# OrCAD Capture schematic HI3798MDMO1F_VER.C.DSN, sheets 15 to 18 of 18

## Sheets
15 SHEET_04: size A3
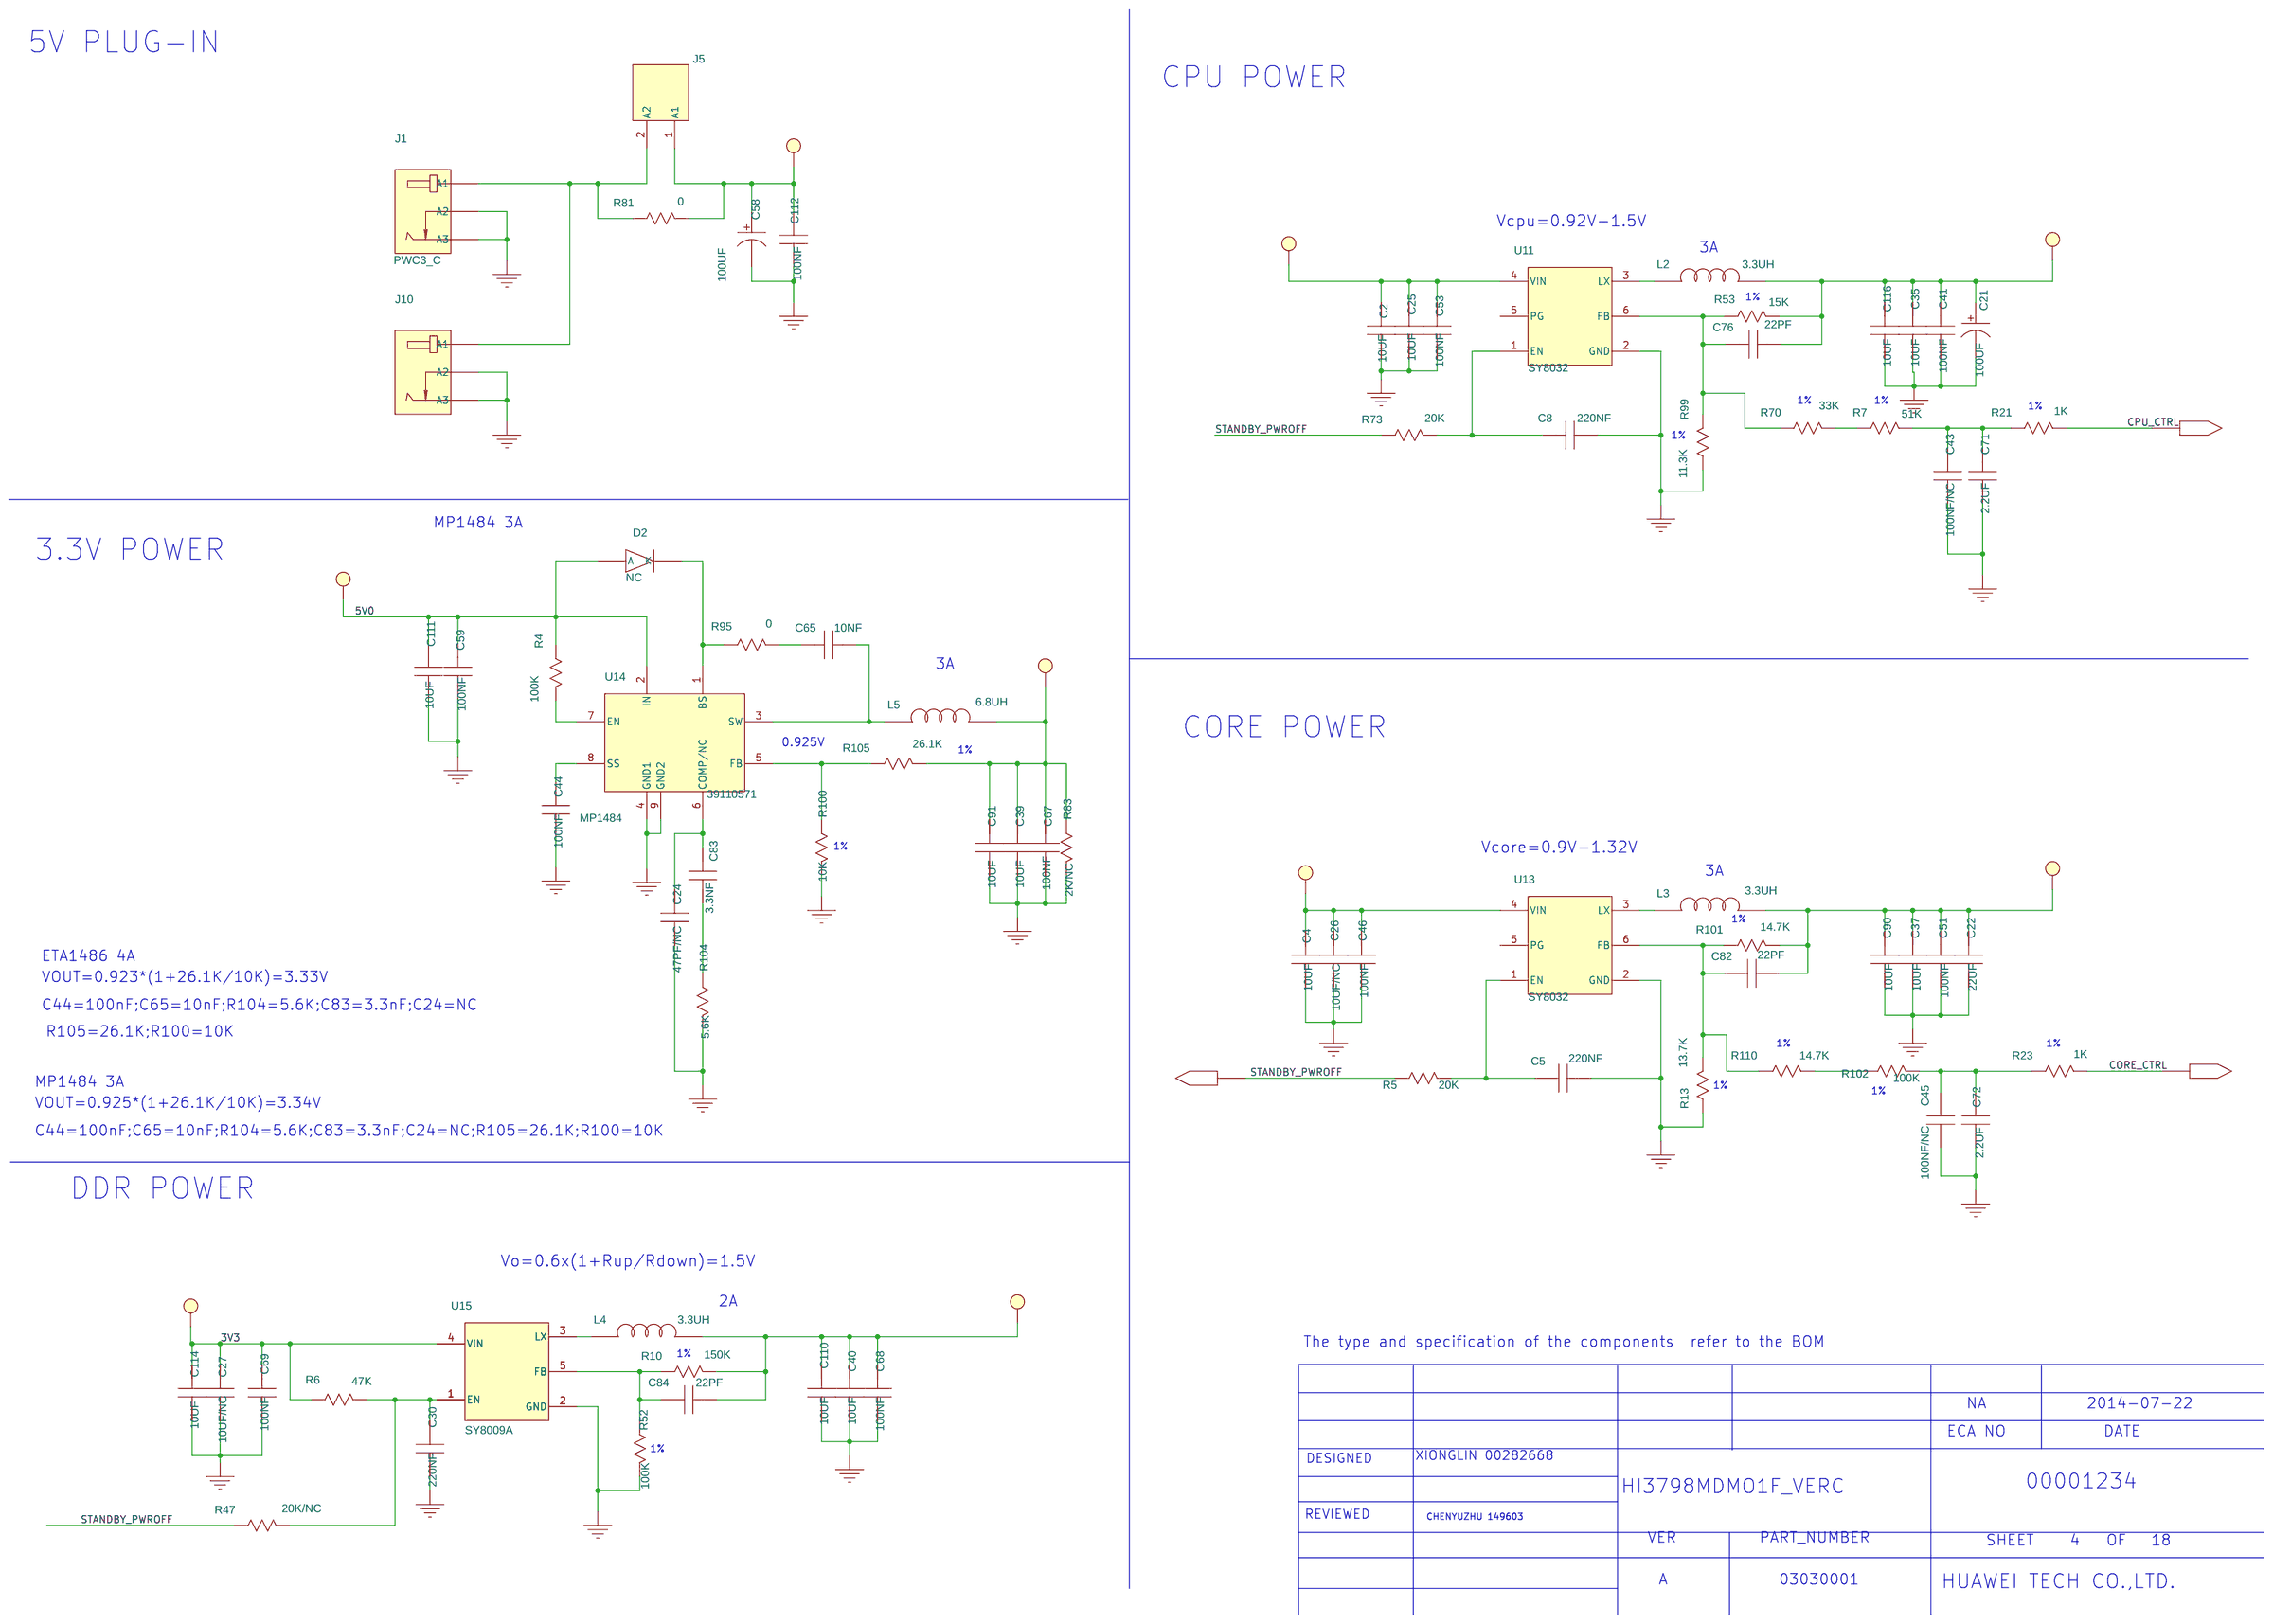
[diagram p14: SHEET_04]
16 SHEET_03: size A3
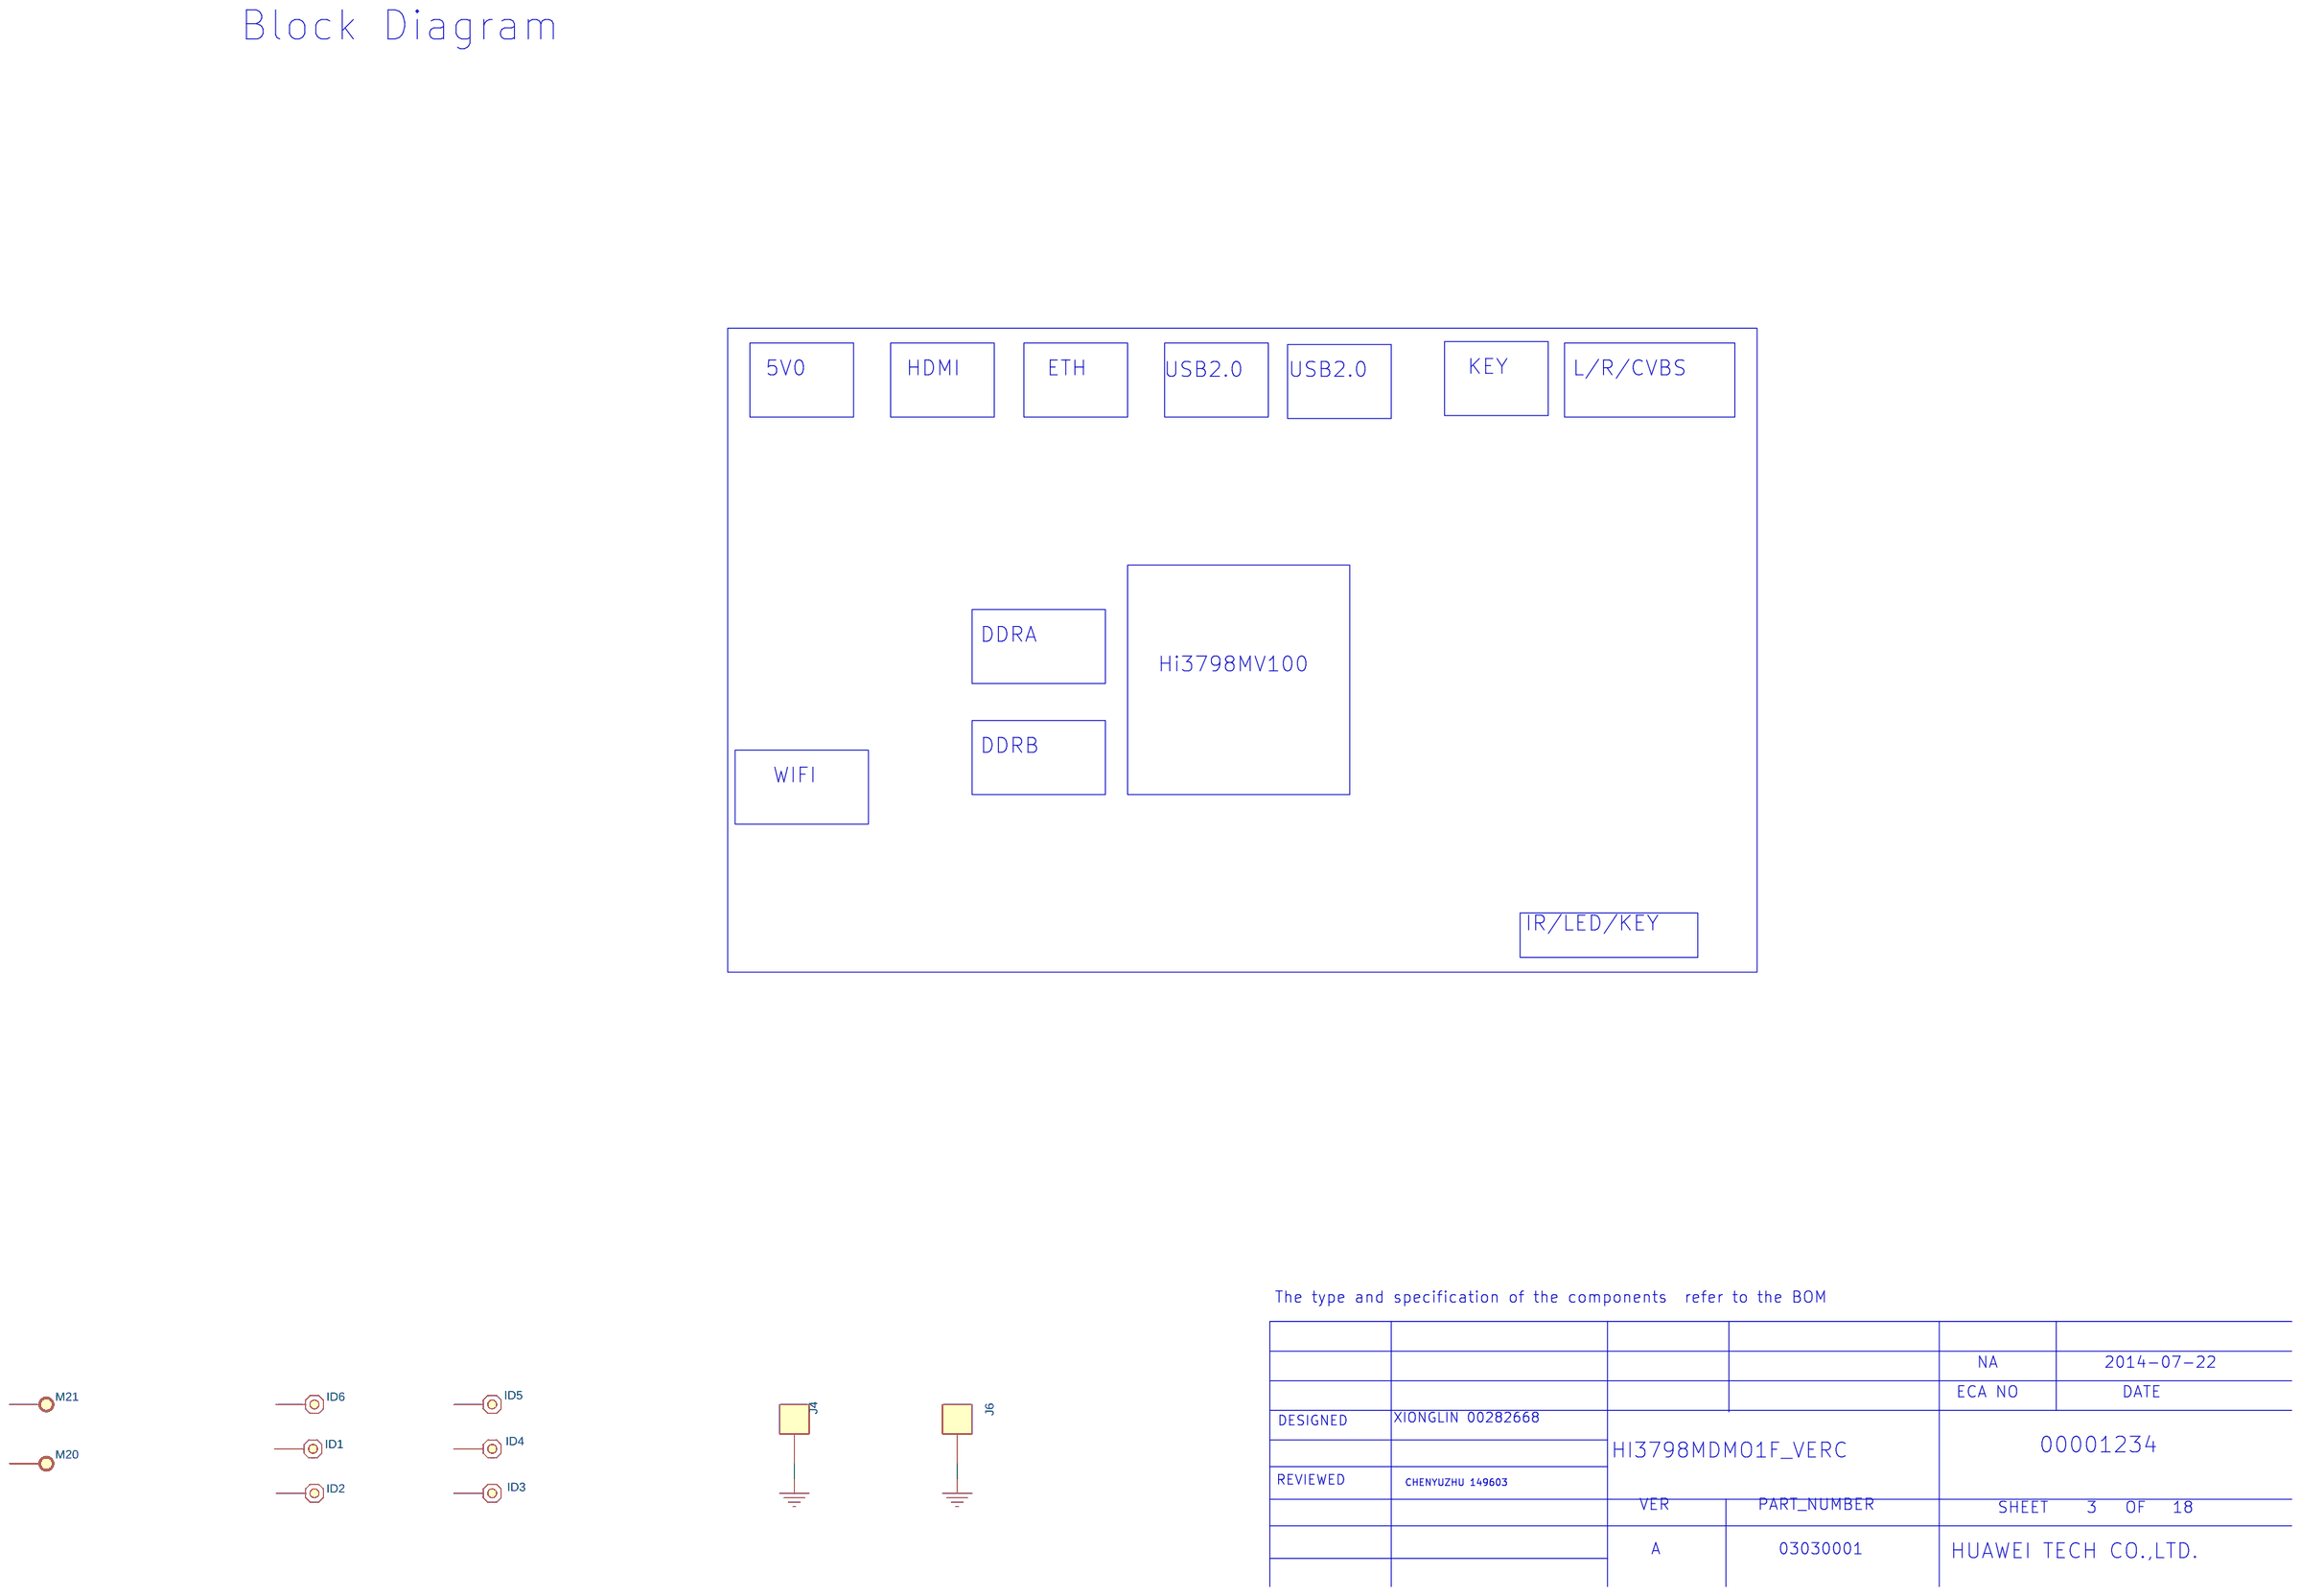
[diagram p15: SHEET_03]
17 SHEET_02
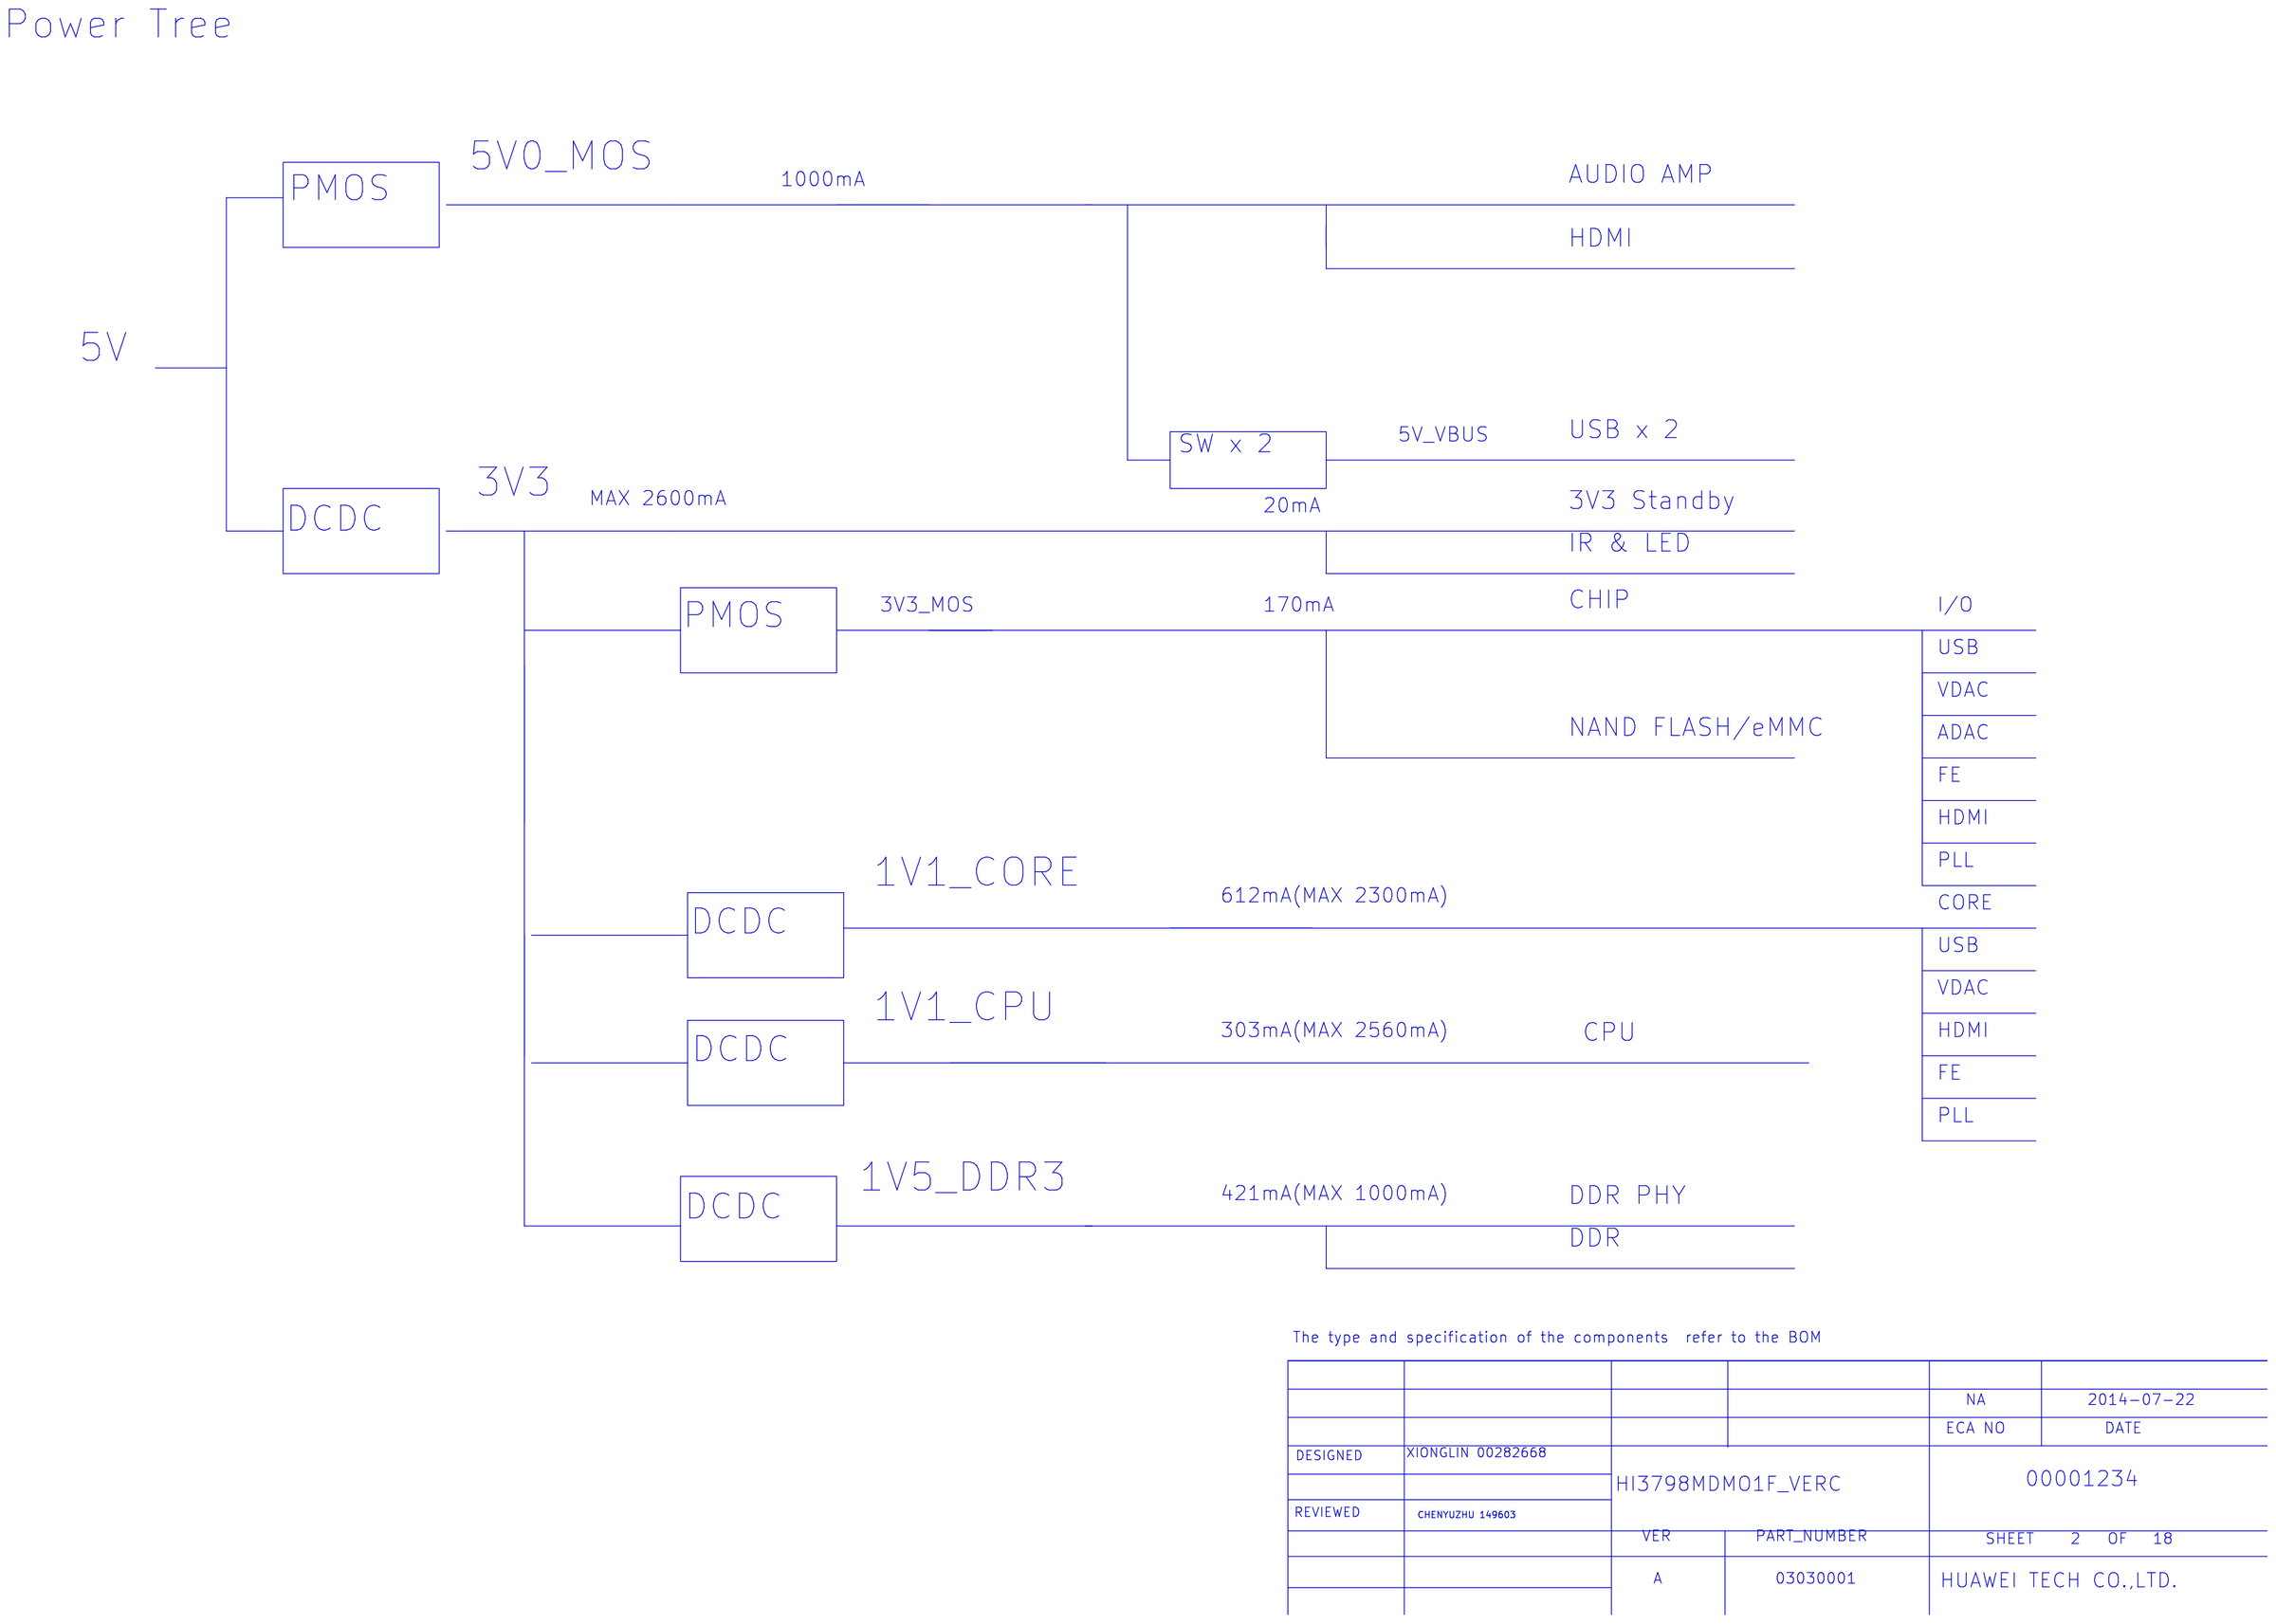
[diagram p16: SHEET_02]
18 SHEET_01
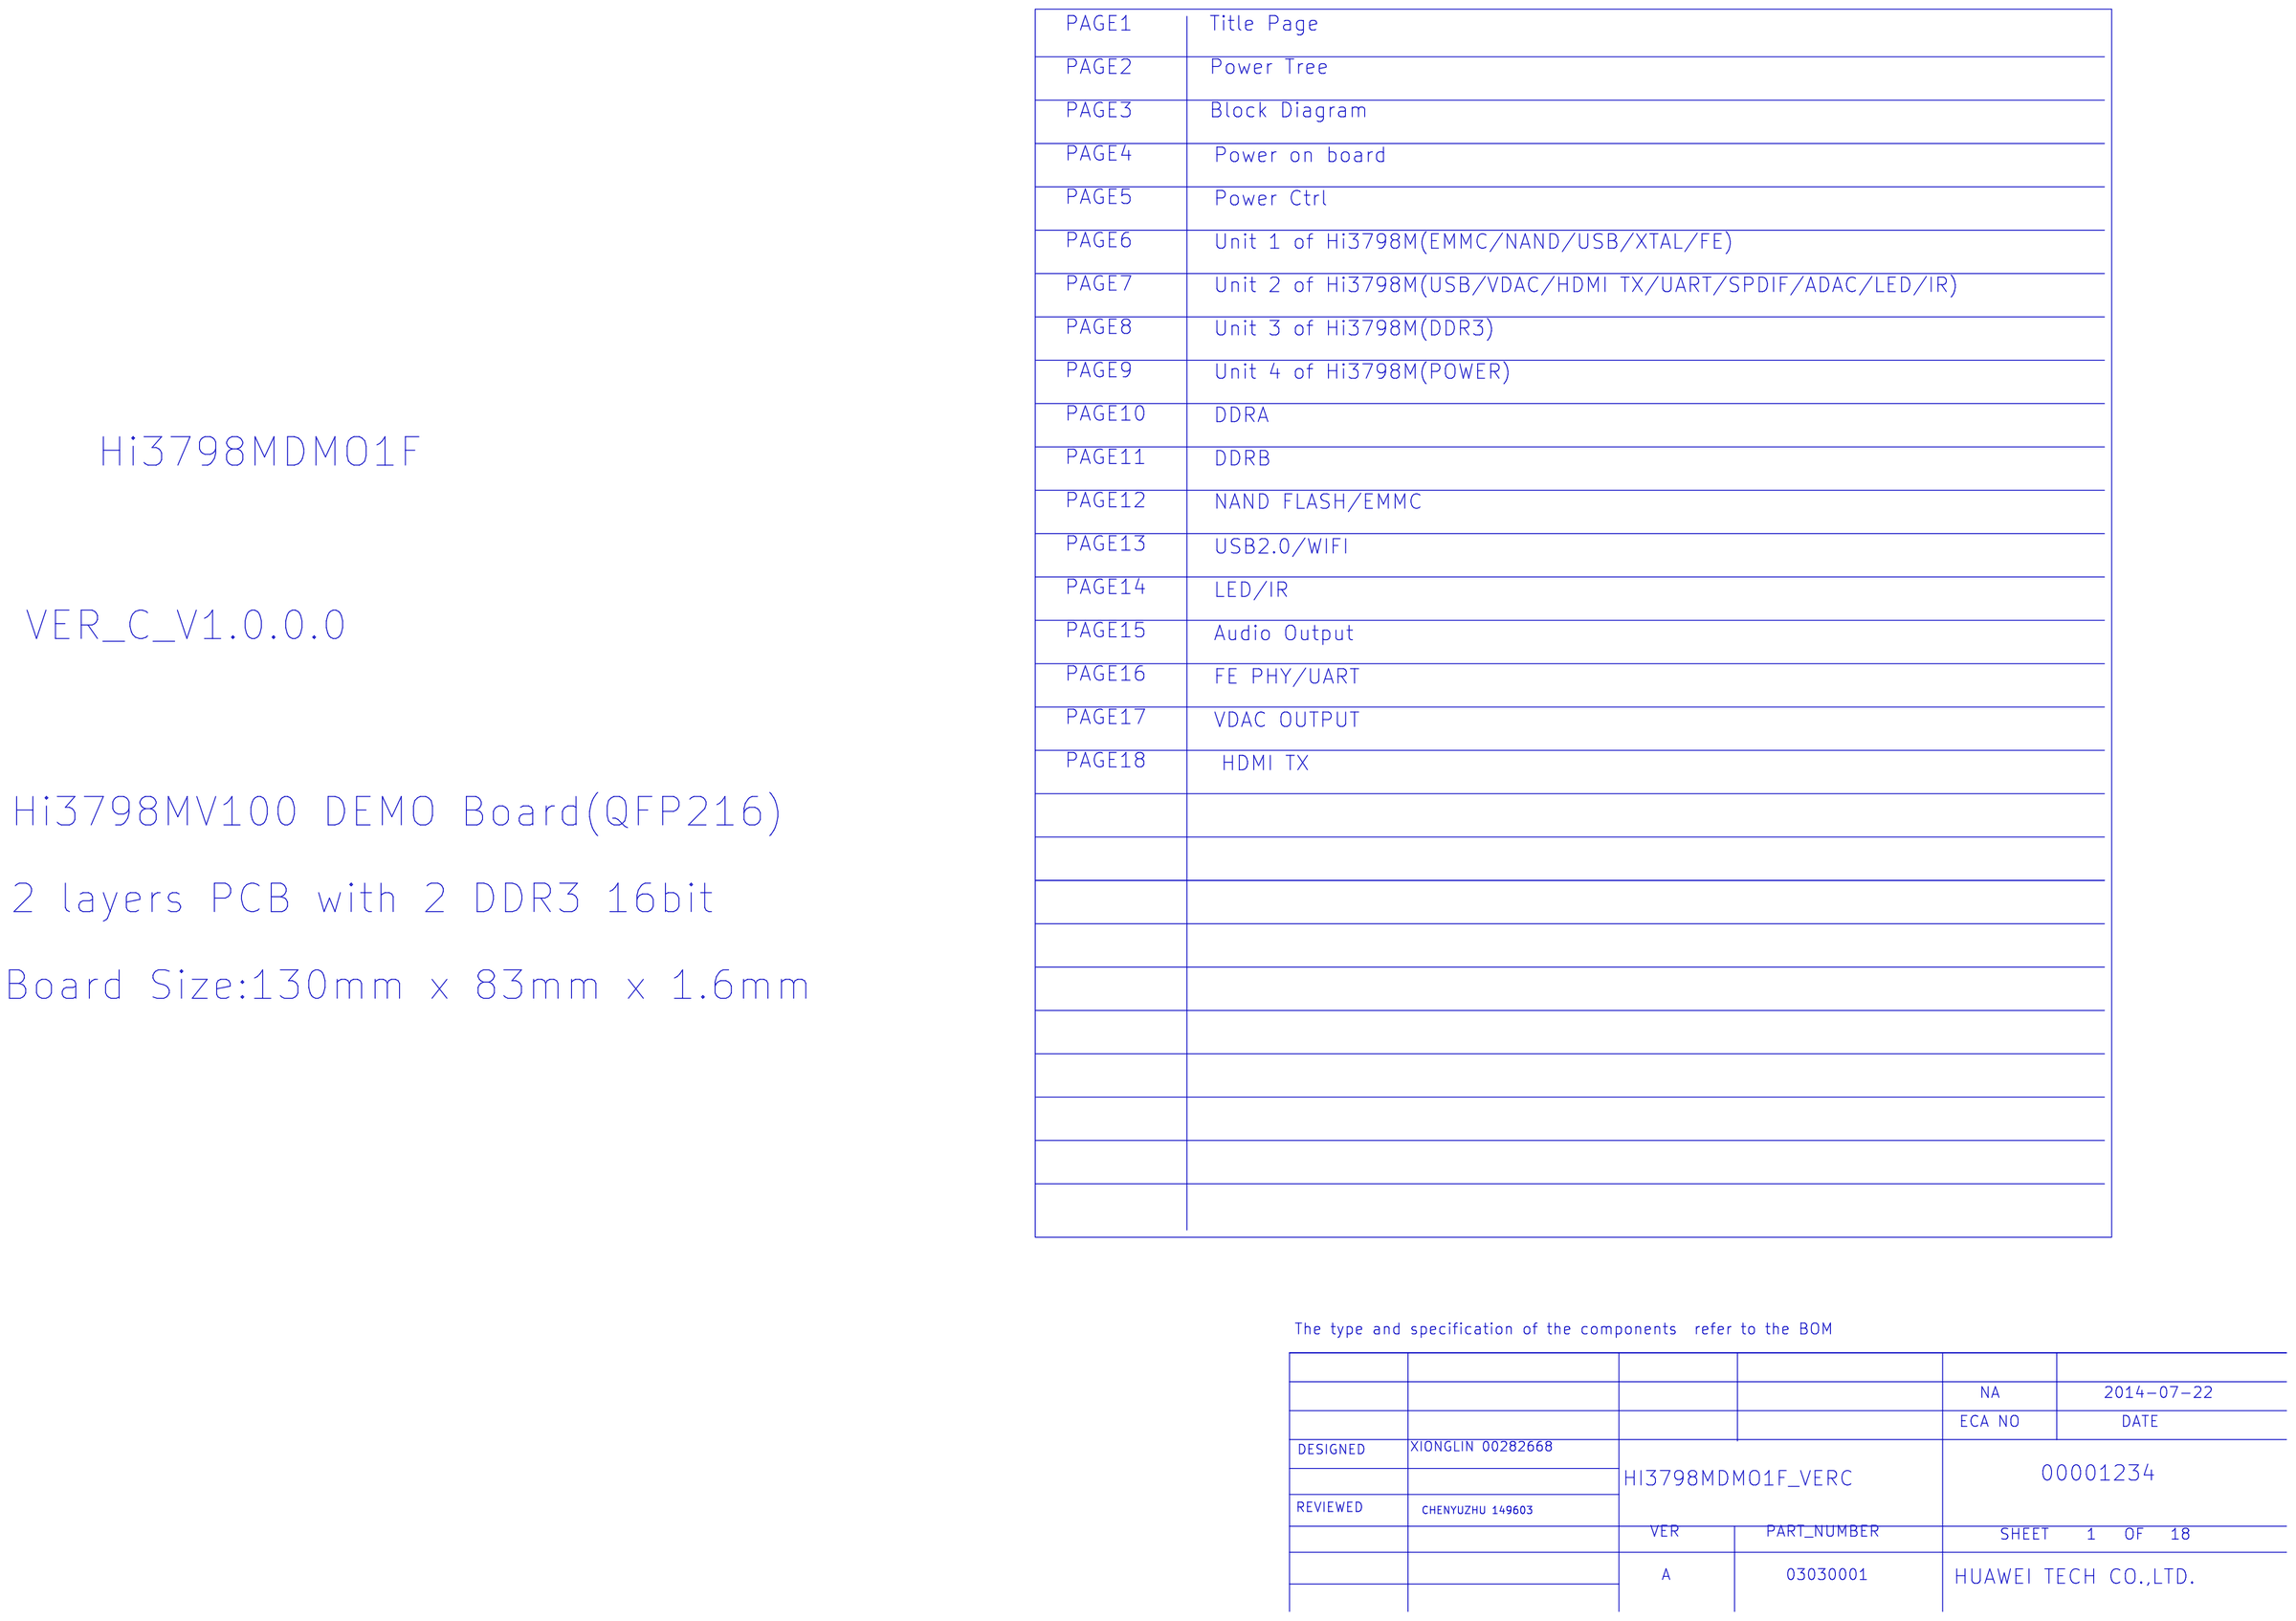
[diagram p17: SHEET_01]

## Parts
sheet SHEET_03
ID1  ID-BOARD  [ID-BOARD]
ID2  ID-BOARD  [ID-BOARD]
ID3  ID-BOARD  [ID-BOARD]
ID4  ID-BOARD  [ID-BOARD]
ID5  ID-BOARD  [ID-BOARD]
ID6  ID-BOARD  [ID-BOARD]
J4  NC  [SIP-1P]
J6  NC  [SIP-1P]
M20  HOLE  [HOLE182-142]
M21  HOLE  [HOLE182-142]
sheet SHEET_04
C2  10UF  [SC0805]
C4  10UF  [SC0805]
C5  220NF  [SC0402]
C8  220NF  [SC0402]
C21  100UF  [SAC6666]
C22  22UF  [SC1206]
C24  47PF/NC  [SC0402]
C25  10UF  [SC0805]
C26  10UF/NC  [SC0805]
C27  10UF/NC  [SC0805]
C30  220NF  [SC0402]
C35  10UF  [SC0603]
C37  10UF  [SC0603]
C39  10UF  [SC0603]
C40  10UF  [SC0603]
C41  100NF  [SC0402]
C43  100NF/NC  [SC0402]
C44  100NF  [SC0402]
C45  100NF/NC  [SC0402]
C46  100NF  [SC0402]
C51  100NF  [SC0402]
C53  100NF  [SC0402]
C58  100UF  [SAC6666]
C59  100NF  [SC0402]
C65  10NF  [SC0402]
C67  100NF  [SC0402]
C68  100NF  [SC0402]
C69  100NF  [SC0402]
C71  2.2UF  [SC0603]
C72  2.2UF  [SC0603]
C76  22PF  [SC0402]
C82  22PF  [SC0402]
C83  3.3NF  [SC0402]
C84  22PF  [SC0402]
C90  10UF  [SC0603]
C91  10UF  [SC0603]
C110  10UF  [SC0603]
C111  10UF  [SC0805]
C112  100NF  [SC0402]
C114  10UF  [SC0805]
C116  10UF  [SC0603]
D2  NC  [HSOD323A]
J1  PWC3_C  [PWC3-RF-A]
J5  NC  [SIP-2P]
J10  NC  [DC-002]
L2  3.3UH  [SWPA4020S]
L3  3.3UH  [SWPA4020S]
L4  3.3UH  [SWPA4020S]
L5  6.8UH  [SWPA5040S]
R4  100K  [SR0402]
R5  20K  [SR0402]
R6  47K  [SR0402]
R7  51K  [SR0402]
R10  150K  [SR0402]
R13  13.7K  [SR0402]
R21  1K  [SR0402]
R23  1K  [SR0402]
R47  20K/NC  [SR0402]
R52  100K  [SR0402]
R53  15K  [SR0402]
R70  33K  [SR0402]
R73  20K  [SR0402]
R81  0  [SR1206]
R83  2K/NC  [SR0805]
R95  0  [SR0402]
R99  11.3K  [SR0402]
R100  10K  [SR0402]
R101  14.7K  [SR0402]
R102  100K  [SR0402]
R104  5.6K  [SR0402]
R105  26.1K  [SR0402]
R110  14.7K  [SR0402]
U11  SY8032  [SOT23_6]
U13  SY8032  [SOT23_6]
U14  MP1484  [SOIC8N]
U15  SY8009A  [SOT23_5]

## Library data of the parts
ID1-ID6 = ID-BOARD: %195%%232%%202%%246%: PCB-MARK点ID-BOARD，亮铜直径40MIL，阻焊开窗直径80MIL，MARK点大小120MIL。; DEVICE: PCB_MARKPOINT_A
J4 J6 = SIP1: %195%%232%%202%%246%: 插针-普通方脚插针-1PIN-单排-直式-5.84MM-2.92MM-2.54MM-THT; %208%%161%%192%%224%%195%%251%%179%%198%: 插针; CODE: 14050101; DEVICE: TSW_101_23_F_S
M20 M21 = HOLE: %195%%232%%202%%246%: 4.0MM铆钉，对应封装孔径162MIL(4.0MM铆接孔的禁布区为300MIL)金属化孔。; DEVICE: RIVET_HOLE162_R4_A
C2 C4 C25-C27 C111 C114 = C: %182%%238%%182%%168%%185%%164%%215%%247%%181%%231%%209%%185%(V): 25; %195%%232%%202%%246%: SMD陶瓷电容-25V-10000NF-+/-20%-X5R-0805; %208%%161%%192%%224%%195%%251%%179%%198%: SMD陶瓷电容; CODE: 8071629; COMPONENT_HIGH_MAX: 1.45MM; DEVICE: C2012X5R1E106KT000N1
C5 C8 C30 = C: %182%%238%%182%%168%%185%%164%%215%%247%%181%%231%%209%%185%(V): 6.3; %195%%232%%202%%246%: SMD陶瓷电容-6.3V-220NF-+/-10%-X5R-0402-BT; %208%%161%%192%%224%%195%%251%%179%%198%: SMD陶瓷电容; CODE: 8070584; COMPONENT_HIGH_MAX: 0.55MM; DEVICE: GRM155R60J224KE01D
C21 C58 = CP: %182%%238%%182%%168%%185%%164%%215%%247%%181%%231%%209%%185%(V): 16; %195%%232%%202%%246%: 非固体SMD铝电容-16V-100UF-+/-20%-6.3*5.4MM-极性-105DEGC-1000H-片式,温度敏感器件-工艺耐温250DEGC,5S; %208%%161%%192%%224%%195%%251%%179%%198%: 非固体SMD铝电容; CODE: 8010269; COMPONENT_HIGH_MAX: 5.7MM; DEVICE: UWT1C101MCL1GB
C22 = C: %182%%238%%182%%168%%185%%164%%215%%247%%181%%231%%209%%185%(V): 6.3; %195%%232%%202%%246%: SMD陶瓷电容-6.3V-47000NF-+/-20%-X5R-1206; %208%%161%%192%%224%%195%%251%%179%%198%: SMD陶瓷电容; CODE: 8070680; COMPONENT_HIGH_MAX: 1.9MM; DEVICE: CM316X5R476M06AT
C24 = C: %182%%238%%182%%168%%185%%164%%215%%247%%181%%231%%209%%185%(V): 50; %195%%232%%202%%246%: SMD陶瓷电容-50V-0.047NF-±5%-NP0-0402; %208%%161%%192%%224%%195%%251%%179%%198%: SMD陶瓷电容; CODE: 8070549; COMPONENT_HIGH_MAX: 0.55MM; DEVICE: C0402C470J5GAC_7867
C35 C37 C39 C40 C90 C91 C110 C116 = C: %182%%238%%182%%168%%185%%164%%215%%247%%181%%231%%209%%185%(V): 6.3; %195%%232%%202%%246%: SMD陶瓷电容-6.3V-10000NF-+/-20%-X5R-0603-BT,TS16949; %208%%161%%192%%224%%195%%251%%179%%198%: SMD陶瓷电容; CODE: 8070649; COMPONENT_HIGH_MAX: 0.9MM; DEVICE: C1608X5R0J106MT0A0E
C41 C43-C46 C51 C53 C59 C67-C69 C112 = C: %182%%238%%182%%168%%185%%164%%215%%247%%181%%231%%209%%185%(V): 16; %195%%232%%202%%246%: SMD陶瓷电容-16V-100NF-±10%-X7R-0402; %208%%161%%192%%224%%195%%251%%179%%198%: SMD陶瓷电容; CODE: 8070614; COMPONENT_HIGH_MAX: 0.6MM; DEVICE: RMEMK105BJ104KV_FR
C65 = C: %182%%238%%182%%168%%185%%164%%215%%247%%181%%231%%209%%185%(V): 16; %195%%232%%202%%246%: SMD陶瓷电容-16V-10NF-+/-10%-X7R-0402; %208%%161%%192%%224%%195%%251%%179%%198%: SMD陶瓷电容; CODE: 8070449; COMPONENT_HIGH_MAX: 0.55MM; DEVICE: GRM155R71C103KA01D
C71 C72 = C: %182%%238%%182%%168%%185%%164%%215%%247%%181%%231%%209%%185%(V): 10; %195%%232%%202%%246%: SMD陶瓷电容-10V-2200NF-+/-10%-X5R-0603; %208%%161%%192%%224%%195%%251%%179%%198%: SMD陶瓷电容; CODE: 8070573; COMPONENT_HIGH_MAX: 0.9MM; DEVICE: GRM188R61A225KE34D
C76 C82 C84 = C: %182%%238%%182%%168%%185%%164%%215%%247%%181%%231%%209%%185%(V): 50; %195%%232%%202%%246%: SMD陶瓷电容-50V-0.022NF-+/-5%-NP0-0402-BT; %208%%161%%192%%224%%195%%251%%179%%198%: SMD陶瓷电容; CODE: 8070545; COMPONENT_HIGH_MAX: 0.55MM; DEVICE: RMUMK105CG220JV_F
C83 = C: %182%%238%%182%%168%%185%%164%%215%%247%%181%%231%%209%%185%(V): 50; %195%%232%%202%%246%: SMD陶瓷电容-50V-3.3NF-±10%-X7R-0402; %208%%161%%192%%224%%195%%251%%179%%198%: SMD陶瓷电容; CODE: 8070621; COMPONENT_HIGH_MAX: 0.55MM; DEVICE: GRM155R71H332KA01D
D2 = D_A: %195%%232%%202%%246%: 肖特基二极管-10V-3A-0.24V-SOD323-BT; %208%%161%%192%%224%%195%%251%%179%%198%: 肖特基二极管; CODE: 15010252; COMPONENT_HIGH_MAX: 1.1MM; DEVICE: BAT60BE6327
J1 = PWC3_C: %195%%232%%202%%246%: IO连接器-DC JACK-3PIN-母座-3.9/1.3MM弯式-5V2A-00482858; CODE: 14240410; COMPONENT_HIGH_MAX: 11.25MM; DEVICE: DC_012_HW
J5 = SIP2: %195%%232%%202%%246%: 插针-普通方脚插针-2PIN-单排-直式-5.84MM-2.92MM-2.54MM-THT; %208%%161%%192%%224%%195%%251%%179%%198%: 插针; CODE: 14050028; COMPONENT_HIGH_MAX: 8.38MM; DEVICE: TSW_102_23_F_S
J10 = PWC3_C: %195%%232%%202%%246%: IO连接器-DC JACK-3PIN-母座-3.9/1.3MM弯式-5V2A-00482858; CODE: *; COMPONENT_HIGH_MAX: 11.25MM; DEVICE: DC_012_HW
L2-L4 = SWPA4020S3R3MT
L5 = SWPA5040S6R8MT
R4 = R: %182%%238%%182%%168%%185%%166%%194%%202%(W): 0.06; %195%%232%%202%%246%: 片式厚膜电阻器-0.0625W-100000OHM-+/-5%-0402; %208%%161%%192%%224%%195%%251%%179%%198%: 片式厚膜电阻器; %215%%232%%214%%181%%212%%202%%208%%237%%198%%171%%178%%238%: +/-5%; CODE: 7090831; COMPONENT_HIGH_MAX: 0.4MM; DEVICE: RK73B1ELTP104J
R5 R47 R73 = R: %182%%238%%182%%168%%185%%166%%194%%202%(W): 0.06; %195%%232%%202%%246%: 片式厚膜电阻器-0.0625W-20000OHM-+/-1%-0402-TS16949; %208%%161%%192%%224%%195%%251%%179%%198%: 片式厚膜电阻器; %215%%232%%214%%181%%212%%202%%208%%237%%198%%171%%178%%238%: +/-1%; CODE: 7091374; COMPONENT_HIGH_MAX: 0.4MM; DEVICE: RC_02W2002FT
R6 = R: %182%%238%%182%%168%%185%%166%%194%%202%(W): 0.06; %195%%232%%202%%246%: 片式厚膜电阻器-0.0625W-47000OHM-+/-5%-0402-ELOM; %208%%161%%192%%224%%195%%251%%179%%198%: 片式厚膜电阻器; %215%%232%%214%%181%%212%%202%%208%%237%%198%%171%%178%%238%: +/-5%; CODE: 7090819; COMPONENT_HIGH_MAX: 0.4MM; DEVICE: RC0402JR_0747K
R7 = R: %182%%238%%182%%168%%185%%166%%194%%202%(W): 0.06; %195%%232%%202%%246%: 片式厚膜电阻器-0.0625W-51000OHM-+/-1%-0402; %208%%161%%192%%224%%195%%251%%179%%198%: 片式厚膜电阻器; %215%%232%%214%%181%%212%%202%%208%%237%%198%%171%%178%%238%: +/-1%; CODE: 7091384; COMPONENT_HIGH_MAX: 0.4MM; DEVICE: RC_02W5102FT
R10 = R: %182%%238%%182%%168%%185%%166%%194%%202%(W): 0.06; %195%%232%%202%%246%: 片式厚膜电阻器-0.0625W-150000OHM-+/-1%-0402; %208%%161%%192%%224%%195%%251%%179%%198%: 片式厚膜电阻器; %215%%232%%214%%181%%212%%202%%208%%237%%198%%171%%178%%238%: +/-1%; CODE: 7090833; COMPONENT_HIGH_MAX: 0.4MM; DEVICE: RK73H1ELTP1503F
R13 = R: %182%%238%%182%%168%%185%%166%%194%%202%(W): 0.06; %195%%232%%202%%246%: 片式厚膜电阻器-0.0625W-13700OHM-+/- 1%-0402-供电专用-供电专用; %208%%161%%192%%224%%195%%251%%179%%198%: 片式厚膜电阻器; %215%%232%%214%%181%%212%%202%%208%%237%%198%%171%%178%%238%: +/- 1%; CODE: 7091435; COMPONENT_HIGH_MAX: 0.4MM; DEVICE: RC0402FR_0713K7L
R21 R23 = R: %182%%238%%182%%168%%185%%166%%194%%202%(W): 0.1; %195%%232%%202%%246%: 片式厚膜电阻器-0.1W-1000OHM-+/-1%-0603; %208%%161%%192%%224%%195%%251%%179%%198%: 片式厚膜电阻器; %215%%232%%214%%181%%212%%202%%208%%237%%198%%171%%178%%238%: +/-1%; CODE: 7092250; COMPONENT_HIGH_MAX: 0.5MM; DEVICE: RK73H1JTTD1001F
R52 = R: %182%%238%%182%%168%%185%%166%%194%%202%(W): 0.06; %195%%232%%202%%246%: 片式厚膜电阻器-0.0625W-100000OHM-+/-5%-0402-BT; %208%%161%%192%%224%%195%%251%%179%%198%: 片式厚膜电阻器; %215%%232%%214%%181%%212%%202%%208%%237%%198%%171%%178%%238%: +/-5%; CODE: 7090831; COMPONENT_HIGH_MAX: 0.4MM; DEVICE: RK73B1ELTP104J
R53 = R: %182%%238%%182%%168%%185%%166%%194%%202%(W): 0.06; %195%%232%%202%%246%: 片式厚膜电阻器-0.0625W-15000OHM-+/-1%-0402-BT; %208%%161%%192%%224%%195%%251%%179%%198%: 片式厚膜电阻器; %215%%232%%214%%181%%212%%202%%208%%237%%198%%171%%178%%238%: +/-1%; CODE: 7091372; COMPONENT_HIGH_MAX: 0.4MM; DEVICE: RC_02W1502FT
R70 = R: %182%%238%%182%%168%%185%%166%%194%%202%(W): 0.06; %195%%232%%202%%246%: 片式厚膜电阻器-0.0625W-33000OHM-+/-5%-0402; %208%%161%%192%%224%%195%%251%%179%%198%: 片式厚膜电阻器; %215%%232%%214%%181%%212%%202%%208%%237%%198%%171%%178%%238%: +/-5%; CODE: 7090828; COMPONENT_HIGH_MAX: 0.4MM; DEVICE: RK73B1ELTP333J
R81 = R: %182%%238%%182%%168%%185%%166%%194%%202%(W): 0.25; %195%%232%%202%%246%: 片式厚膜电阻器-0.25W-0OHM-<50MOHM-1206-2A-BT; %208%%161%%192%%224%%195%%251%%179%%198%: 片式厚膜电阻器; %215%%232%%214%%181%%212%%202%%208%%237%%198%%171%%178%%238%: <50MOHM; CODE: 7090002; COMPONENT_HIGH_MAX: 0.7MM; DEVICE: RC1206JR_070RL
R83 = R: %182%%238%%182%%168%%185%%166%%194%%202%(W): 0.13; %195%%232%%202%%246%: 片式厚膜电阻器-0.125W-2000OHM-+/-1%-0805; %208%%161%%192%%224%%195%%251%%179%%198%: 片式厚膜电阻器; %215%%232%%214%%181%%212%%202%%208%%237%%198%%171%%178%%238%: +/-1%; CODE: 7090225; COMPONENT_HIGH_MAX: 0.65MM; DEVICE: RK73H2ATTD2001F
R95 = R: %182%%238%%182%%168%%185%%166%%194%%202%(W): 0.06; %195%%232%%202%%246%: 片式厚膜电阻器-0.0625W-0OHM-< 50MOHM-0402-1A-BT; %208%%161%%192%%224%%195%%251%%179%%198%: 片式厚膜电阻器; %215%%232%%214%%181%%212%%202%%208%%237%%198%%171%%178%%238%: < 50MOHM; CODE: 7090800; DEVICE: RC0402JR_070R
R99 = R: %182%%238%%182%%168%%185%%166%%194%%202%(W): 0.06; %195%%232%%202%%246%: 片式厚膜电阻器-0.0625W-11300OHM-+/-1%-0402; %208%%161%%192%%224%%195%%251%%179%%198%: 片式厚膜电阻器; %215%%232%%214%%181%%212%%202%%208%%237%%198%%171%%178%%238%: +/-1%; CODE: 7090816; COMPONENT_HIGH_MAX: 0.4MM; DEVICE: RC0402FR_0711K3
R100 = R: %182%%238%%182%%168%%185%%166%%194%%202%(W): 0.06; %195%%232%%202%%246%: 片式厚膜电阻器-0.0625W-10000OHM-+/-1%-0402-BT; %208%%161%%192%%224%%195%%251%%179%%198%: 片式厚膜电阻器; %215%%232%%214%%181%%212%%202%%208%%237%%198%%171%%178%%238%: +/-1%; CODE: 7090867; COMPONENT_HIGH_MAX: 0.4MM; DEVICE: RK73H1ETTP1002F
R101 R110 = R: %182%%238%%182%%168%%185%%166%%194%%202%(W): 0.06; %195%%232%%202%%246%: 片式厚膜电阻器-0.0625W-14700OHM-+/-1%-0402; %208%%161%%192%%224%%195%%251%%179%%198%: 片式厚膜电阻器; %215%%232%%214%%181%%212%%202%%208%%237%%198%%171%%178%%238%: +/-1%; CODE: *; COMPONENT_HIGH_MAX: 0.4MM; DEVICE: RK73H1ETTD7502F
R102 = R: %182%%238%%182%%168%%185%%166%%194%%202%(W): 0.06; %195%%232%%202%%246%: 片式厚膜电阻器-0.0625W-100000OHM-+/-1%-0402; %208%%161%%192%%224%%195%%251%%179%%198%: 片式厚膜电阻器; %215%%232%%214%%181%%212%%202%%208%%237%%198%%171%%178%%238%: +/-1%; CODE: 7090875; COMPONENT_HIGH_MAX: 0.4MM; DEVICE: RK73H1ETTP1003F
R104 = R: %182%%238%%182%%168%%185%%166%%194%%202%(W): 0.06; %195%%232%%202%%246%: 片式厚膜电阻器-0.0625W-5600OHM-+/-1%-0402-BT; %208%%161%%192%%224%%195%%251%%179%%198%: 片式厚膜电阻器; %215%%232%%214%%181%%212%%202%%208%%237%%198%%171%%178%%238%: +/-1%; CODE: 7091275; COMPONENT_HIGH_MAX: 0.4MM; DEVICE: RK73H1ETTP5601F
R105 = R: %182%%238%%182%%168%%185%%166%%194%%202%(W): 0.06; %195%%232%%202%%246%: 片式厚膜电阻器-0.0625W-26100OHM-+/-1%-0402; %208%%161%%192%%224%%195%%251%%179%%198%: 片式厚膜电阻器; %215%%232%%214%%181%%212%%202%%208%%237%%198%%171%%178%%238%: +/-5%; CODE: *; COMPONENT_HIGH_MAX: 0.4MM; DEVICE: RK73B1ETTP273J
U11 U13 = SY8032
U14 = MP1484: CODE: 39110571
U15 = SY8009A

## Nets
1V1_CORE: C22.1(A) C37.1(A) C51.1(A) C82.2(B) C90.1(A) L3.2(B) R101.2(B) ; also on sheet 10 12 13
1V1_CPU: C21.1 C35.1(A) C41.1(A) C76.2(B) C116.1(A) L2.2(B) R53.2(B) ; also on sheet 10
1V5_DDR3: C40.1(A) C68.1(A) C84.2(B) C110.1(A) L4.2(B) R10.2(B) ; also on sheet 8 9 11
3V3: C2.1(A) C4.1(A) C25.1(A) C26.1(A) C27.1(A) C39.1(A) C46.1(A) C53.1(A) C67.1(A) C69.1(A) C91.1(A) C114.1(A) L5.2(B) R6.1(A) R83.1(A) R105.2(B) U11.4(VIN) U13.4(VIN) U15.4(VIN) ; also on sheet 3 5 10 13 14
5V0: C58.1 C59.1(A) C111.1(A) C112.1(A) D2.2(A) J5.1(A1) R4.1(A) R81.2(B) U14.2(IN) ; also on sheet 14
GND: C2.2(B) C4.2(B) C5.2(B) C8.2(B) C21.2 C22.2(B) C24.2(B) C25.2(B) C26.2(B) C27.2(B) C30.2(B) C35.2(B) C37.2(B) C39.2(B) C40.2(B) C41.2(B) C43.2(B) C44.2(B) C45.2(B) C46.2(B) C51.2(B) C53.2(B) C58.2 C59.2(B) C67.2(B) C68.2(B) C69.2(B) C71.2(B) C72.2(B) C90.2(B) C91.2(B) C110.2(B) C111.2(B) C112.2(B) C114.2(B) C116.2(B) J1.2(A2) J1.3(A3) J4.1 J6.1 J10.2(A2) J10.3(A3) R13.1(A) R52.2(B) R83.2(B) R99.1(A) R100.2(B) R104.2(B) U11.2(GND) U13.2(GND) U14.4(GND1) U14.9(GND2) U15.2(GND) ; also on sheet 1 2 3 4 5 6 7 8 9 10 11 12 13 14
CORE_CTRL: R23.2(B) ; also on sheet 12
CPU_CTRL: R21.2(B) ; also on sheet 12
STANDBY_PWROFF: R5.1(A) R47.1(A) R73.1(A) ; also on sheet 13 14
N338390: C82.1(A) R13.2(B) R101.1(A) R110.1(A) U13.6(FB)
N338426: C5.1(A) R5.2(B) U13.1(EN)
N338674: C76.1(A) R53.1(A) R70.1(A) R99.2(B) U11.6(FB)
N338710: C8.1(A) R73.2(B) U11.1(EN)
N338726: L3.1(A) U13.3(LX)
N338730: C45.1(A) C72.1(A) R23.1(A) R102.2(B)
N338750: L2.1(A) U11.3(LX)
N338754: C43.1(A) C71.1(A) R7.2(B) R21.1(A)
N338774: L4.1(A) U15.3(LX)
N338830: R7.1(A) R70.2(B)
N338834: C65.2(B) L5.1(A) U14.3(SW)
N338850: C65.1(A) R95.2(B)
N338854: C44.1(A) U14.8(SS)
N338862: R4.2(B) U14.7(EN)
N338870: C24.1(A) C83.1(A) U14.6(COMP/NC)
N338886: C83.2(B) R104.1(A)
N338890: R100.1(A) R105.1(A) U14.5(FB)
N338902: C30.1(A) R6.2(B) R47.2(B) U15.1(EN)
N338986: J1.1(A1) J5.2(A2) J10.1(A1) R81.1(A)
N339078: D2.1(K) R95.1(A) U14.1(BS)
N339094: R102.1(A) R110.2(B)
N339098: C84.1(A) R10.1(A) R52.1(A) U15.5(FB)

Not connected (* = marked no-connect by the designer): ID1 1; ID2 1; ID3 1; ID4 1; ID5 1; ID6 1; M20 1(GND); M21 1(GND); U11 5(PG); U13 5(PG)

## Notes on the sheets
sheet 15
- 5V PLUG-IN
- CPU POWER
- Vcpu=0.92V-1.5V
- 3A
- 1%
- 1%
- 1%
- 1%
- 1%
- MP1484 3A
- 3.3V POWER
- 3A
- CORE POWER
- 0.925V
- 1%
- 1%
- Vcore=0.9V-1.32V
- 3A
- 1%
- ETA1486 4A
- VOUT=0.923*(1+26.1K/10K)=3.33V
- C44=100nF;C65=10nF;R104=5.6K;C83=3.3nF;C24=NC
- R105=26.1K;R100=10K
- 1%
- 1%
- MP1484 3A
- 1%
- 1%
- VOUT=0.925*(1+26.1K/10K)=3.34V
- C44=100nF;C65=10nF;R104=5.6K;C83=3.3nF;C24=NC;R105=26.1K;R100=10K
- DDR POWER
- Vo=0.6x(1+Rup/Rdown)=1.5V
- 2A
- 1%
- The type and specification of the components  refer to the BOM
- NA
- 2014-07-22
- ECA NO
- DATE
- 1%
- XIONGLIN 00282668
- DESIGNED
- HI3798MDMO1F_VERC
- 00001234
- REVIEWED
- CHENYUZHU 149603
- VER
- PART_NUMBER
- SHEET
- 4
- OF
- 18
- A
- 03030001
- HUAWEI TECH CO.,LTD.
sheet 16
- Block Diagram
- 5V0
- HDMI
- ETH
- USB2.0
- USB2.0
- KEY
- L/R/CVBS
- DDRA
- Hi3798MV100
- DDRB
- WIFI
- IR/LED/KEY
- The type and specification of the components  refer to the BOM
- NA
- 2014-07-22
- ECA NO
- DATE
- XIONGLIN 00282668
- DESIGNED
- HI3798MDMO1F_VERC
- 00001234
- REVIEWED
- CHENYUZHU 149603
- VER
- PART_NUMBER
- SHEET
- 3
- OF
- 18
- A
- 03030001
- HUAWEI TECH CO.,LTD.
sheet 17
- Power Tree
- 5V0_MOS
- 1000mA
- AUDIO AMP
- PMOS
- HDMI
- 5V
- USB x 2
- SW x 2
- 5V_VBUS
- 3V3
- MAX 2600mA
- 3V3 Standby
- DCDC
- 20mA
- IR & LED
- CHIP
- PMOS
- 3V3_MOS
- 170mA
- I/O
- USB
- VDAC
- NAND FLASH/eMMC
- ADAC
- FE
- HDMI
- 1V1_CORE
- PLL
- 612mA(MAX 2300mA)
- DCDC
- CORE
- USB
- 1V1_CPU
- VDAC
- 303mA(MAX 2560mA)
- CPU
- HDMI
- DCDC
- FE
- PLL
- 1V5_DDR3
- DCDC
- 421mA(MAX 1000mA)
- DDR PHY
- DDR
- The type and specification of the components  refer to the BOM
- NA
- 2014-07-22
- ECA NO
- DATE
- DESIGNED
- XIONGLIN 00282668
- HI3798MDMO1F_VERC
- 00001234
- REVIEWED
- CHENYUZHU 149603
- VER
- PART_NUMBER
- SHEET
- 2
- OF
- 18
- A
- 03030001
- HUAWEI TECH CO.,LTD.
sheet 18
- PAGE1
- Title Page
- PAGE2
- Power Tree
- PAGE3
- Block Diagram
- PAGE4
- Power on board
- PAGE5
- Power Ctrl
- PAGE6
- Unit 1 of Hi3798M(EMMC/NAND/USB/XTAL/FE)
- PAGE7
- Unit 2 of Hi3798M(USB/VDAC/HDMI TX/UART/SPDIF/ADAC/LED/IR)
- PAGE8
- Unit 3 of Hi3798M(DDR3)
- PAGE9
- Unit 4 of Hi3798M(POWER)
- PAGE10
- DDRA
- Hi3798MDMO1F
- PAGE11
- DDRB
- PAGE12
- NAND FLASH/EMMC
- PAGE13
- USB2.0/WIFI
- PAGE14
- LED/IR
- VER_C_V1.0.0.0
- PAGE15
- Audio Output
- PAGE16
- FE PHY/UART
- PAGE17
- VDAC OUTPUT
- PAGE18
- HDMI TX
- Hi3798MV100 DEMO Board(QFP216)
- 2 layers PCB with 2 DDR3 16bit
- Board Size:130mm x 83mm x 1.6mm
- The type and specification of the components  refer to the BOM
- NA
- 2014-07-22
- ECA NO
- DATE
- DESIGNED
- XIONGLIN 00282668
- 00001234
- HI3798MDMO1F_VERC
- REVIEWED
- CHENYUZHU 149603
- VER
- PART_NUMBER
- SHEET
- 1
- OF
- 18
- A
- 03030001
- HUAWEI TECH CO.,LTD.
